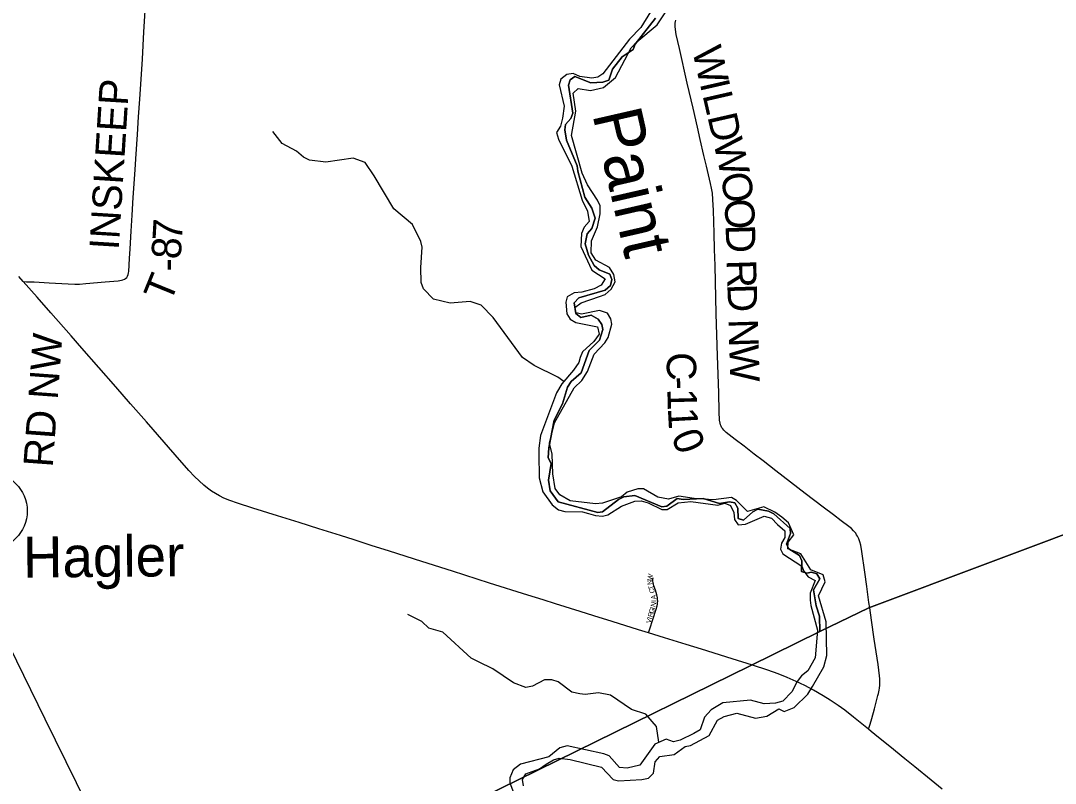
# Model space of a CAD drawing. Extents: x -51392 to 1635000, y 156707 to 696232.
# Drawn here: x 118169 to 128704, y 502833 to 510595 of the extents above; entities that cross this region are included whole.
import ezdxf

# ---------------------------------------------------------------- set-up
doc = ezdxf.new("R2010")
doc.units = 0
for name, color, linetype in [('GM_X_County_Road', 7, 'Continuous'), ('GM_X_County_Road_Text', 7, 'Continuous'), ('GM_X_Major_River', 7, 'Continuous'), ('GM_X_Major_River_Text', 7, 'Continuous'), ('GM_X_Minor_River', 7, 'Continuous'), ('GM_X_Rail_Line', 7, 'Continuous'), ('GM_X_State_Route', 7, 'Continuous'), ('GM_X_Township', 7, 'Continuous'), ('GM_X_Township_Road', 7, 'Continuous'), ('GM_X_Township_Road_Text', 7, 'Continuous'), ('GM_X_Township_Subdivision', 7, 'Continuous'), ('GM_X_Township_Subdivision_Text', 7, 'Continuous'), ('GM_X_Unincorporated', 7, 'Continuous'), ('GM_X_Unincorporated_Text', 7, 'Continuous')]:
    doc.layers.add(name, color=color, linetype=linetype)

msp = doc.modelspace()

# ---------------------------------------------------------------- linework, layer by layer
at = {"layer": 'GM_X_County_Road'}
for points in [[(126814, 504621), (126806, 504674), (126784, 504836), (126763, 504982), (126734, 505194), (126723, 505258), (126714, 505290), (126703, 505321), (126697, 505336), (126689, 505350), (126681, 505364), (126671, 505378), (126650, 505403), (126627, 505426), (126602, 505447), (126523, 505506), (126444, 505565), (126339, 505644), (126158, 505784), (125859, 506014), (125729, 506114), (125638, 506184), (125534, 506264), (125443, 506333), (125353, 506405), (125329, 506428), (125318, 506440), (125308, 506453), (125301, 506467), (125295, 506483), (125291, 506498), (125286, 506531), (125281, 506613), (125277, 506809), (125265, 507186), (125252, 507613), (125239, 508104), (125235, 508268), (125230, 508432), (125223, 508662), (125218, 508776), (125212, 508841), (125204, 508890), (125194, 508938), (125152, 509114), (125126, 509225), (125089, 509385), (125060, 509513), (125016, 509705), (124956, 509960), (124876, 510312), (124844, 510456), (124836, 510505), (124833, 510537), (124833, 510554), (124834, 510570), (124837, 510586), (124841, 510602)], [(126803, 503383), (126812, 503415), (126818, 503436), (126835, 503494), (126862, 503591), (126897, 503728), (126902, 503746), (126906, 503764), (126910, 503782), (126914, 503803), (126917, 503831), (126917, 503845), (126918, 503862), (126916, 503895), (126914, 503927), (126900, 504041), (126860, 504301), (126832, 504495), (126814, 504621)]]:
    msp.add_lwpolyline(points, dxfattribs=at)
at = {"layer": 'GM_X_Major_River'}
for points in [[(124221, 507938), (124209, 508013), (124165, 508083), (124025, 508157), (123978, 508232), (123982, 508356), (124043, 508498), (124069, 508628), (124068, 508710), (124042, 508770), (123940, 508925), (123887, 509045), (123776, 509426), (123823, 509675), (123796, 509857), (123846, 509905), (123972, 509884), (124104, 509914), (124225, 510016), (124384, 510318), (124442, 510380), (124651, 510553), (124869, 510889)], [(124654, 510800), (124483, 510526), (124368, 510408), (124097, 510054), (124045, 510020), (123985, 510011), (123861, 510027), (123795, 510057), (123731, 510047), (123668, 510000), (123652, 509941), (123703, 509725), (123685, 509605), (123667, 509523), (123626, 509459), (123644, 509389), (123781, 509116), (123886, 508769), (123939, 508658), (123957, 508552), (123905, 508494), (123880, 508428), (123874, 508298), (123983, 508057), (124121, 507969), (124078, 507903), (124010, 507867), (123882, 507833), (123806, 507827), (123734, 507786), (123720, 507732), (123731, 507611), (123765, 507557), (123821, 507523), (124043, 507478), (124060, 507406), (124006, 507330), (123888, 507226), (123865, 507168), (123851, 507116), (123799, 507040), (123678, 506898), (123626, 506808), (123462, 506374), (123444, 506246), (123445, 506188), (123450, 505943), (123486, 505801), (123581, 505668), (123645, 505618), (123709, 505600), (123889, 505597), (123951, 505581), (124021, 505559), (124093, 505551), (124147, 505565), (124286, 505654), (124422, 505706), (124488, 505708), (124558, 505687), (124698, 505621), (124750, 505621), (124862, 505689), (124994, 505700), (125266, 505665), (125338, 505685), (125398, 505661), (125432, 505589), (125438, 505518), (125476, 505464), (125550, 505472), (125738, 505552), (125814, 505531), (125876, 505469), (125949, 505403), (125949, 505335), (125915, 505277), (125907, 505218), (125931, 505168), (126124, 505043), (126142, 504991)], [(123290, 502806), (123278, 502873), (123314, 502929), (123451, 502980), (123521, 503028), (123593, 503072), (123653, 503090), (123763, 503077), (124083, 502998), (124203, 502872), (124255, 502857), (124495, 502873), (124563, 502885), (124611, 502937), (124628, 503051), (124678, 503107), (124824, 503128), (124934, 503208), (124988, 503218), (125179, 503321), (125264, 503477), (125332, 503513), (125462, 503547), (125652, 503496), (125766, 503518), (125888, 503590), (125942, 503563), (126046, 503605), (126185, 503741), (126233, 503817), (126348, 504019), (126377, 504133), (126370, 504478), (126291, 504740), (126360, 504884), (126340, 504955), (126216, 505005), (126111, 505168), (125981, 505220), (125983, 505288), (126043, 505362), (125986, 505483), (125920, 505543), (125848, 505593), (125736, 505648), (125568, 505600), (125458, 505713), (125405, 505743), (125224, 505717), (125028, 505732), (124870, 505755), (124764, 505725), (124656, 505747), (124512, 505830), (124452, 505830), (124344, 505796), (124286, 505750), (124094, 505683), (124022, 505679), (123764, 505708), (123658, 505768), (123612, 505833), (123589, 505983), (123581, 506183), (123554, 506296), (123603, 506504), (123806, 506858), (123882, 506934), (123939, 507026), (124008, 507202), (124118, 507316), (124152, 507372), (124187, 507506), (124177, 507560), (124143, 507618), (124061, 507646), (123881, 507609), (123825, 507623), (123811, 507677), (123876, 507723), (124064, 507787), (124122, 507810), (124182, 507862), (124221, 507938)], [(126142, 504991), (126188, 504935), (126258, 504897), (126209, 504769), (126207, 504699), (126213, 504643), (126282, 504392), (126259, 504109), (126184, 503977), (126118, 503928), (126074, 503870), (126021, 503766), (125929, 503670), (125855, 503648), (125740, 503642), (125601, 503679), (125318, 503654), (125200, 503580), (125132, 503508), (125089, 503378), (125023, 503340), (124885, 503272), (124816, 503256), (124741, 503283), (124626, 503231), (124473, 503017), (124345, 502987), (124265, 502994), (124160, 503114), (124108, 503134), (123734, 503214), (123660, 503196), (123547, 503104), (123257, 503029), (123185, 502971), (123150, 502889), (123150, 502837), (123198, 502713)]]:
    msp.add_lwpolyline(points, dxfattribs=at)
at = {"layer": 'GM_X_Minor_River'}
for points in [[(121768, 509017), (121678, 509153), (121554, 509196), (121275, 509154), (121110, 509176), (121048, 509206), (120976, 509269), (120832, 509346), (120735, 509467)], [(123698, 506924), (123639, 506967), (123397, 507085), (123279, 507168), (122981, 507576), (122857, 507700), (122745, 507737), (122543, 507721), (122371, 507762), (122269, 507866), (122248, 507930), (122244, 508085), (122257, 508289), (122245, 508349), (122160, 508522), (121970, 508679), (121768, 509017)], [(124668, 503251), (124643, 503413), (124535, 503538), (124388, 503586), (124174, 503729), (124054, 503754), (123916, 503736), (123864, 503744), (123782, 503761), (123642, 503865), (123578, 503885), (123502, 503886), (123380, 503822), (123314, 503810), (123186, 503855), (122978, 503997), (122829, 504068), (122755, 504108), (122466, 504372), (122326, 504414), (122254, 504479), (122110, 504551)]]:
    msp.add_lwpolyline(points, dxfattribs=at)
at = {"layer": 'GM_X_Rail_Line'}
msp.add_lwpolyline([(118950, 502403), (118418, 503485), (117763, 504818)], dxfattribs=at)
at = {"layer": 'GM_X_State_Route'}
msp.add_lwpolyline([(127551, 502772), (127438, 502865), (127273, 503000), (127172, 503084), (127020, 503208), (126905, 503301), (126828, 503362), (126803, 503383), (126650, 503508), (126559, 503578), (126492, 503626), (126411, 503681), (126341, 503724), (126241, 503782), (126154, 503828), (126065, 503871), (125975, 503911), (125883, 503947), (125775, 503986), (125619, 504037), (125619, 504037), (125415, 504100), (125102, 504198), (124945, 504245), (124726, 504313), (124560, 504364), (124459, 504395), (124193, 504479), (124005, 504538), (123865, 504582), (123614, 504660), (123489, 504700), (123332, 504749), (122941, 504872), (122566, 504991), (122254, 505092), (121925, 505196), (121737, 505255), (121566, 505310), (121425, 505355), (121206, 505424), (121003, 505489), (120783, 505556), (120533, 505635), (120377, 505685), (120300, 505713), (120239, 505737), (120195, 505758), (120152, 505782), (120111, 505808), (120071, 505836), (120033, 505867), (119985, 505911), (119938, 505957), (119882, 506017), (119741, 506177), (119450, 506511), (119287, 506695), (119137, 506869), (118791, 507264), (118683, 507387), (118477, 507621), (118336, 507782), (118196, 507941), (118152, 507991)], dxfattribs=at)
at = {"layer": 'GM_X_Township'}
for points in [[(124634, 510621), (124426, 510356), (124404, 510304), (124295, 510229), (124196, 510103), (124157, 509991), (124095, 509969), (123973, 509964), (123813, 510029), (123763, 509993), (123746, 509939), (123792, 509655), (123770, 509601), (123718, 509539), (123709, 509483), (123725, 509380), (123835, 509117), (123841, 509065), (123913, 508798), (123986, 508689), (124020, 508585), (123983, 508481), (123937, 508427), (123916, 508323), (123949, 508210), (124007, 508104), (124058, 508059), (124168, 508017), (124188, 507960), (124174, 507900), (124121, 507851), (123852, 507776), (123806, 507724), (123821, 507616), (123873, 507574), (123979, 507599), (124049, 507558), (124085, 507504), (124097, 507454), (124064, 507344), (123957, 507240), (123875, 507012), (123775, 506923), (123736, 506865), (123685, 506697), (123600, 506531), (123546, 506247), (123541, 506145), (123569, 506088), (123542, 505918), (123559, 505810), (123642, 505699), (124044, 505590), (124094, 505598), (124256, 505721), (124312, 505749), (124422, 505762), (124696, 505646), (124748, 505654), (124855, 505733), (124913, 505723), (125119, 505732), (125285, 505681), (125387, 505698), (125439, 505688), (125471, 505633), (125474, 505529), (125528, 505511), (125625, 505598), (125675, 505622), (125783, 505603), (125839, 505575), (126003, 505428), (126006, 505375), (125965, 505269), (125991, 505219), (126099, 505152), (126123, 505098), (126120, 504990), (126172, 504971), (126222, 504981), (126276, 504967), (126306, 504913), (126243, 504801), (126270, 504640), (126303, 504534), (126307, 504377), (125597, 504028), (120292, 501424)], [(131842, 506508), (126804, 504618), (126307, 504377), (126303, 504534), (126270, 504640), (126243, 504801), (126306, 504913), (126276, 504967), (126222, 504981), (126172, 504971), (126120, 504990), (126123, 505098), (126099, 505152), (125991, 505219), (125965, 505269), (126006, 505375), (126003, 505428), (125839, 505575), (125783, 505603), (125675, 505622), (125625, 505598), (125528, 505511), (125474, 505529), (125471, 505633), (125439, 505688), (125387, 505698), (125285, 505681), (125119, 505732), (124913, 505723), (124855, 505733), (124748, 505654), (124696, 505646), (124422, 505762), (124312, 505749), (124256, 505721), (124094, 505598), (124044, 505590), (123642, 505699), (123559, 505810), (123542, 505918), (123569, 506088), (123541, 506145), (123546, 506247), (123600, 506531), (123685, 506697), (123736, 506865), (123775, 506923), (123875, 507012), (123957, 507240), (124064, 507344), (124097, 507454), (124085, 507504), (124049, 507558), (123979, 507599), (123873, 507574), (123821, 507616), (123806, 507724), (123852, 507776), (124121, 507851), (124174, 507900), (124188, 507960), (124168, 508017), (124058, 508059), (124007, 508104), (123949, 508210), (123916, 508323), (123937, 508427), (123983, 508481), (124020, 508585), (123986, 508689), (123913, 508798), (123841, 509065), (123835, 509117), (123725, 509380), (123709, 509483), (123718, 509539), (123770, 509601), (123792, 509655), (123746, 509939), (123763, 509993), (123813, 510029), (123973, 509964), (124095, 509969), (124157, 509991), (124196, 510103), (124295, 510229), (124404, 510304), (124426, 510356), (124634, 510621)], [(120292, 501424), (125597, 504028), (126307, 504377), (126804, 504618), (131842, 506508)]]:
    msp.add_lwpolyline(points, dxfattribs=at)
at = {"layer": 'GM_X_Township_Road'}
msp.add_lwpolyline([(118196, 507941), (118230, 507939), (118306, 507937), (118458, 507929), (118654, 507917), (118719, 507914), (118769, 507915), (118834, 507919), (119030, 507938), (119161, 507949), (119194, 507953), (119210, 507957), (119225, 507963), (119238, 507972), (119249, 507983), (119258, 507996), (119264, 508012), (119267, 508028), (119269, 508044), (119276, 508175), (119283, 508274), (119295, 508454), (119305, 508617), (119316, 508797), (119335, 509076), (119342, 509190), (119358, 509436), (119370, 509616), (119381, 509796), (119408, 510205), (119424, 510483), (119436, 510696)], dxfattribs=at)
at = {"layer": 'GM_X_Township_Subdivision'}
msp.add_lwpolyline([(124560, 504364), (124574, 504407), (124605, 504499), (124641, 504607), (124649, 504639), (124652, 504655), (124654, 504671), (124655, 504687), (124654, 504704), (124653, 504720), (124647, 504752), (124633, 504798), (124616, 504844), (124611, 504860), (124608, 504876), (124606, 504892), (124606, 504908), (124608, 504924)], dxfattribs=at)
at = {"layer": 'GM_X_Unincorporated'}
msp.add_circle((117843, 505605), 393, dxfattribs=at)

# ---------------------------------------------------------------- texts
at = {"layer": 'GM_X_County_Road_Text'}
for s, rotation, p in [('W', 282.899, (125004, 510299)), ('I', 282.9004, (125082, 509960)), ('L', 282.9, (125110, 509840)), ('D', 282.8994, (125160, 509621)), ('W', 282.8393, (125219, 509364)), ('O', 279.2271, (125295, 509030)), ('O', 272.1088, (125336, 508779)), ('D', 271.7371, (125346, 508516)), ('R', 271.7329, (125357, 508160)), ('D', 271.7347, (125364, 507914)), ('N', 271.7335, (125375, 507557)), ('W', 271.7352, (125383, 507293)), ('C', 271.3621, (124744, 507218)), ('-', 271.3819, (124750, 506971)), ('1', 271.471, (124753, 506848)), ('1', 273.1762, (124758, 506653)), ('0', 290.7014, (124789, 506371))]:
    msp.add_text(s, height=300, rotation=rotation, dxfattribs=at).set_placement(p)
at = {"layer": 'GM_X_Major_River_Text'}
msp.add_text('Paint', height=500, rotation=282.8971, dxfattribs=at).set_placement((123988, 509646))
at = {"layer": 'GM_X_Township_Road_Text'}
for s, rotation, p in [('INSKEEP', 86.4058, (119167, 508257)), ('7', 86.5334, (119809, 508346)), ('8', 86.6379, (119798, 508162)), ('-', 90.5534, (119800, 508044)), ('T', 67.798, (119691, 507710)), ('RD NW', 85.7926, (118495, 506044))]:
    msp.add_text(s, height=300, rotation=rotation, dxfattribs=at).set_placement(p)
at = {"layer": 'GM_X_Township_Subdivision_Text'}
for s, rotation, p in [('W', 78.4109, (124596, 504896)), ('N', 97.7693, (124602, 504857)), ('T', 109.385, (124617, 504814)), ('C', 108.7661, (124629, 504776)), ('A', 97.7951, (124641, 504709)), ('G', 74.0047, (124612, 504558)), ('I', 73.9565, (124624, 504601)), ('N', 77.6484, (124631, 504625)), ('I', 90.4041, (124642, 504680)), ('V', 74.0047, (124583, 504457)), ('I', 73.9565, (124595, 504499)), ('R', 74.0063, (124601, 504520))]:
    msp.add_text(s, height=50, rotation=rotation, dxfattribs=at).set_placement(p)
at = {"layer": 'GM_X_Unincorporated_Text'}
msp.add_text('Hagler', height=417, rotation=0.5386, dxfattribs=at).set_placement((118194, 504926))

doc.saveas('drawing.dxf')
